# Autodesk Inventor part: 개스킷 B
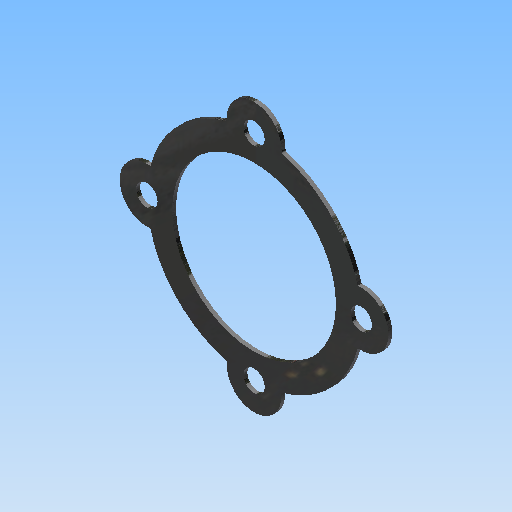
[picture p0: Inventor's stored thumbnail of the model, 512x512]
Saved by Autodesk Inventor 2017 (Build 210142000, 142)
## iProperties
Created: 2020-03
Part Number: 개스킷 B
Material: 고무
Document SubType Name: Modeling
Designer: mduedu
Density: 0.93 g/cm^3
Mass: 1.13966 g
Surface Area: 28.6179 cm^2
Volume: 1.22544 cm^3
Appearance: 고무 - 검은색 - 버전 1.1
Author: mduedu
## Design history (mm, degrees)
sketch "스케치1" dims "d1" = 55
  geometry: C1 r 21 at (0, 0); C2 r 7 at (0, 27.5); C3 r 7 at (-23.816, -13.75); C4 r 7 at (23.816, -13.75); 2 further points
  constraints: 4 centre point, 2 coincident, 2 vertical alignment, 9 other
  dimensions: "d0" = 42 diameter of C1; "d2" = 14 diameter of C2; "d5" = 360 deg dimension on point (0, 0) C2.centre (derived)
extrude "돌출1" new body sketch "스케치1" distance "d7" = 1; taper "d8" = 0 deg
extrude "돌출3" join sketch "스케치1" stored distance "d19" = 10; taper "d20" = 0 deg
fillet "모깎기1" dims "d11" = 1
extrude "돌출2" cut sketch "스케치1" stored distance "d9" = 1; taper "d10" = 0 deg
sketch "스케치2"
  geometry: C1 r 21 at (0, 0) reference; A1 r 7 centre (0, 27.5) between (6.999, 27.373) and (-6.999, 27.373) reference; A2 r 27.5 centre (0, 0) between (26.609, 6.943) and (7.718, 26.395) reference; A3 r 1 centre (7.999, 27.355) between (6.999, 27.373) and (7.718, 26.395) reference; A4 r 7 centre (0, 27.5) between (6.999, 27.373) and (-6.999, 27.373) reference; A5 r 1 centre (-7.999, 27.355) between (-7.718, 26.395) and (-6.999, 27.373) reference; A6 r 7 centre (0, -27.5) between (-6.943, -26.609) and (6.943, -26.609) reference; A7 r 7 centre (-27.5, 0) between (-26.609, 6.943) and (-26.609, -6.943) reference; A8 r 7 centre (27.5, 0) between (26.609, -6.943) and (26.609, 6.943) reference; A9 r 27.5 centre (0, 0) between (-26.609, -6.943) and (-6.943, -26.609) reference; A10 r 27.5 centre (0, 0) between (6.943, -26.609) and (26.609, -6.943) reference; A11 r 27.5 centre (0, 0) between (-7.718, 26.395) and (-26.609, 6.943) reference; 4 further points
hole "구멍1" sketch "스케치2" diameter "d12" = 5.5; stored, may be unused: countersink angle "d16" = 90 deg, drill point angle "d18" = 118 deg; dims "d13" = 6, "d14" = 4, "d15" = 2, "d17" = 8
node "솔리드1"
pattern_circular "원형 패턴1" dims angle "d22" = 360 deg
node "투영된 루프1"
